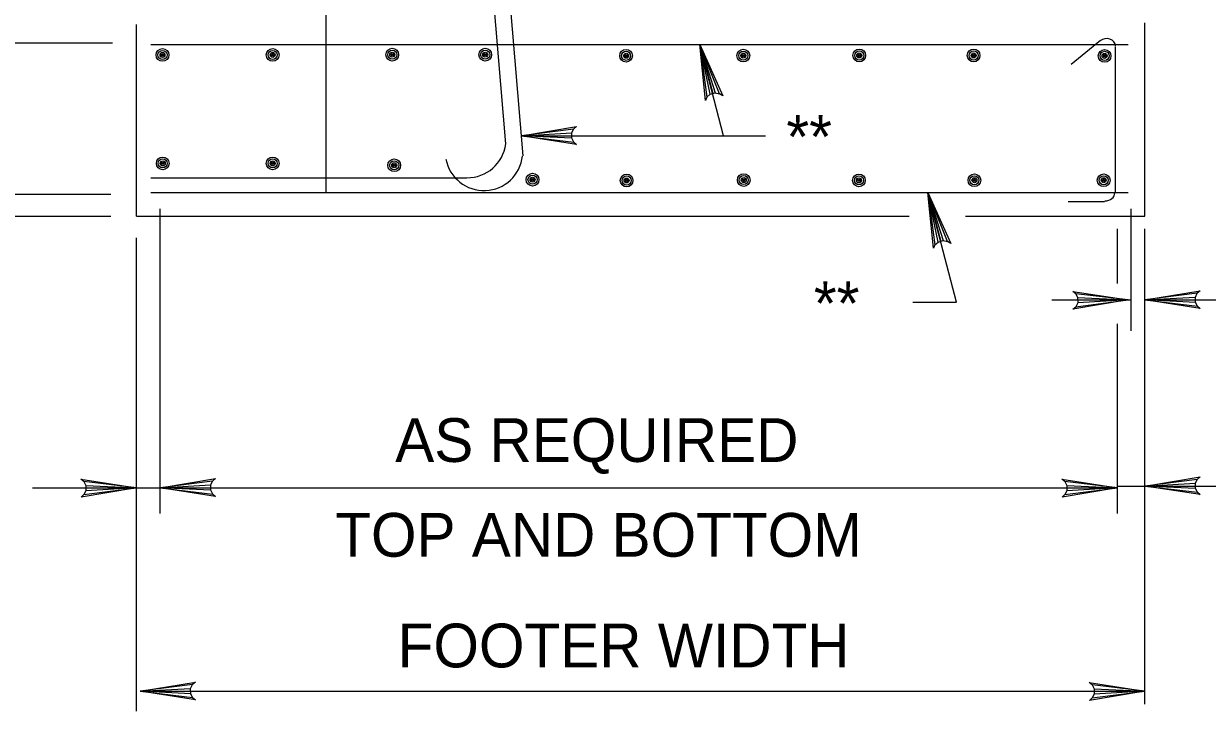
# Model space of a CAD drawing. Extents: x 639011 to 639866, y 298840 to 300028.
# Drawn here: x 639301.8 to 639383, y 299490 to 299537.2 of the extents above; entities that cross this region are included whole.
import ezdxf

# ---------------------------------------------------------------- set-up
doc = ezdxf.new("R2010")
doc.units = 0
doc.layers.add('2', color=7, linetype='Continuous')

msp = doc.modelspace()

# ---------------------------------------------------------------- linework, layer by layer
at = {"layer": '2'}
for p, q in [((639331.736, 299566.393), (639334.86, 299528.911)), ((639334.303, 299548.842), (639336.053, 299528.092)), ((639322.553, 299525.592), (639322.553, 299543.967)), ((639309.553, 299523.967), (639309.553, 299537.092)), ((639378.678, 299523.967), (639378.678, 299537.217)), ((639293.678, 299535.842), (639307.928, 299535.842)), ((639310.553, 299535.717), (639377.553, 299535.717)), ((639349.803, 299529.467), (639348.178, 299535.717)), ((639348.892, 299532.313), (639348.178, 299535.717)), ((639348.178, 299535.717), (639348.669, 299532.115)), ((639348.563, 299531.889), (639348.178, 299535.717)), ((639348.178, 299535.717), (639349.241, 299532.407)), ((639349.527, 299532.349), (639348.178, 299535.717)), ((639348.178, 299535.717), (639349.747, 299532.204)), ((639348.178, 299535.717), (639349.066, 299532.36)), ((639375.635, 299535.99), (639373.635, 299534.365)), ((639376.678, 299525.592), (639376.678, 299535.592)), ((639348.669, 299532.115), (639348.563, 299531.889)), ((639348.669, 299532.115), (639348.892, 299532.313)), ((639348.892, 299532.313), (639349.241, 299532.407)), ((639349.241, 299532.407), (639349.527, 299532.349)), ((639349.747, 299532.204), (639349.527, 299532.349)), ((639335.928, 299529.467), (639339.722, 299530.101)), ((639339.526, 299529.925), (639335.928, 299529.467)), ((639339.399, 299529.663), (639339.526, 299529.925)), ((639339.722, 299530.101), (639339.526, 299529.925)), ((639335.928, 299529.467), (639339.399, 299529.663)), ((639335.928, 299529.467), (639339.4, 299529.482)), ((639335.928, 299529.467), (639352.678, 299529.467)), ((639339.401, 299529.301), (639335.928, 299529.467)), ((639335.928, 299529.467), (639339.537, 299529.036)), ((639339.73, 299528.877), (639335.928, 299529.467)), ((639339.401, 299529.301), (639339.399, 299529.663)), ((639339.537, 299529.036), (639339.401, 299529.301)), ((639339.537, 299529.036), (639339.73, 299528.877)), ((639310.553, 299526.592), (639332.207, 299526.592)), ((639277.303, 299525.467), (639307.803, 299525.467)), ((639310.553, 299525.592), (639377.553, 299525.592)), ((639365.765, 299518.071), (639363.803, 299525.592)), ((639364.519, 299522.189), (639363.803, 299525.592)), ((639363.803, 299525.592), (639364.297, 299521.991)), ((639364.191, 299521.764), (639363.803, 299525.592)), ((639363.803, 299525.592), (639364.869, 299522.283)), ((639365.154, 299522.226), (639363.803, 299525.592)), ((639363.803, 299525.592), (639365.375, 299522.08)), ((639363.803, 299525.592), (639364.694, 299522.236)), ((639373.428, 299524.967), (639375.928, 299524.967)), ((639311.178, 299503.592), (639311.178, 299524.467)), ((639377.759, 299516.092), (639377.759, 299524.467)), ((639266.178, 299523.967), (639307.803, 299523.967)), ((639309.553, 299523.967), (639362.53, 299523.967)), ((639366.384, 299523.967), (639378.678, 299523.967)), ((639309.553, 299490.026), (639309.553, 299522.467)), ((639376.803, 299519.342), (639376.803, 299523.092)), ((639378.678, 299490.526), (639378.678, 299523.092)), ((639364.297, 299521.991), (639364.191, 299521.764)), ((639364.297, 299521.991), (639364.519, 299522.189)), ((639364.519, 299522.189), (639364.869, 299522.283)), ((639364.869, 299522.283), (639365.154, 299522.226)), ((639365.375, 299522.08), (639365.154, 299522.226)), ((639373.944, 299518.647), (639373.751, 299518.807)), ((639373.751, 299518.807), (639377.553, 299518.217)), ((639373.944, 299518.647), (639374.079, 299518.383)), ((639377.553, 299518.217), (639373.944, 299518.647)), ((639374.079, 299518.383), (639377.553, 299518.217)), ((639374.079, 299518.383), (639374.082, 299518.021)), ((639378.678, 299518.217), (639382.472, 299518.851)), ((639382.276, 299518.675), (639378.678, 299518.217)), ((639378.678, 299518.217), (639382.149, 299518.413)), ((639382.149, 299518.413), (639382.276, 299518.675)), ((639382.151, 299518.051), (639382.149, 299518.413)), ((639382.472, 299518.851), (639382.276, 299518.675)), ((639362.782, 299518.071), (639365.765, 299518.071)), ((639372.303, 299518.217), (639377.759, 299518.217)), ((639377.553, 299518.217), (639373.758, 299517.582)), ((639373.758, 299517.582), (639373.954, 299517.759)), ((639373.954, 299517.759), (639377.553, 299518.217)), ((639374.082, 299518.021), (639373.954, 299517.759)), ((639377.553, 299518.217), (639374.081, 299518.202)), ((639377.553, 299518.217), (639374.082, 299518.021)), ((639378.678, 299518.217), (639382.15, 299518.232)), ((639378.678, 299518.217), (639406.277, 299518.217)), ((639382.151, 299518.051), (639378.678, 299518.217)), ((639378.678, 299518.217), (639382.287, 299517.786)), ((639382.48, 299517.627), (639378.678, 299518.217)), ((639382.287, 299517.786), (639382.151, 299518.051)), ((639382.287, 299517.786), (639382.48, 299517.627)), ((639376.803, 299503.592), (639376.803, 299516.592)), ((639302.428, 299505.342), (639311.178, 299505.342)), ((639305.944, 299505.772), (639305.751, 299505.932)), ((639305.751, 299505.932), (639309.553, 299505.342)), ((639309.553, 299505.342), (639305.758, 299504.707)), ((639305.944, 299505.772), (639306.079, 299505.508)), ((639309.553, 299505.342), (639305.944, 299505.772)), ((639305.954, 299504.884), (639309.553, 299505.342)), ((639306.079, 299505.508), (639309.553, 299505.342)), ((639306.079, 299505.508), (639306.082, 299505.146)), ((639309.553, 299505.342), (639306.081, 299505.327)), ((639309.553, 299505.342), (639306.082, 299505.146)), ((639311.178, 299505.342), (639314.972, 299505.976)), ((639314.776, 299505.8), (639311.178, 299505.342)), ((639311.178, 299505.342), (639314.649, 299505.538)), ((639311.178, 299505.342), (639314.65, 299505.357)), ((639311.178, 299505.342), (639376.803, 299505.342)), ((639314.651, 299505.176), (639311.178, 299505.342)), ((639311.178, 299505.342), (639314.787, 299504.911)), ((639314.98, 299504.752), (639311.178, 299505.342)), ((639314.649, 299505.538), (639314.776, 299505.8)), ((639314.651, 299505.176), (639314.649, 299505.538)), ((639314.972, 299505.976), (639314.776, 299505.8)), ((639373.194, 299505.772), (639373.001, 299505.932)), ((639373.001, 299505.932), (639376.803, 299505.342)), ((639376.803, 299505.342), (639373.008, 299504.707)), ((639373.194, 299505.772), (639373.329, 299505.508)), ((639376.803, 299505.342), (639373.194, 299505.772)), ((639373.204, 299504.884), (639376.803, 299505.342)), ((639373.329, 299505.508), (639376.803, 299505.342)), ((639373.329, 299505.508), (639373.332, 299505.146)), ((639376.803, 299505.342), (639373.331, 299505.327)), ((639376.803, 299505.342), (639373.332, 299505.146)), ((639376.803, 299505.467), (639386.678, 299505.467)), ((639378.678, 299505.467), (639382.472, 299506.101)), ((639382.276, 299505.925), (639378.678, 299505.467)), ((639378.678, 299505.467), (639382.149, 299505.663)), ((639378.678, 299505.467), (639382.15, 299505.482)), ((639382.151, 299505.301), (639378.678, 299505.467)), ((639378.678, 299505.467), (639382.287, 299505.036)), ((639382.48, 299504.877), (639378.678, 299505.467)), ((639382.149, 299505.663), (639382.276, 299505.925)), ((639382.151, 299505.301), (639382.149, 299505.663)), ((639382.472, 299506.101), (639382.276, 299505.925)), ((639305.758, 299504.707), (639305.954, 299504.884)), ((639306.082, 299505.146), (639305.954, 299504.884)), ((639314.787, 299504.911), (639314.651, 299505.176)), ((639314.787, 299504.911), (639314.98, 299504.752)), ((639373.008, 299504.707), (639373.204, 299504.884)), ((639373.332, 299505.146), (639373.204, 299504.884)), ((639382.287, 299505.036), (639382.151, 299505.301)), ((639382.287, 299505.036), (639382.48, 299504.877)), ((639309.803, 299491.401), (639313.597, 299492.035)), ((639313.401, 299491.859), (639309.803, 299491.401)), ((639309.803, 299491.401), (639313.274, 299491.597)), ((639313.274, 299491.597), (639313.401, 299491.859)), ((639313.276, 299491.235), (639313.274, 299491.597)), ((639313.597, 299492.035), (639313.401, 299491.859)), ((639375.069, 299491.831), (639374.876, 299491.991)), ((639374.876, 299491.991), (639378.678, 299491.401)), ((639375.069, 299491.831), (639375.204, 299491.567)), ((639378.678, 299491.401), (639375.069, 299491.831)), ((639375.204, 299491.567), (639378.678, 299491.401)), ((639375.204, 299491.567), (639375.207, 299491.205)), ((639309.803, 299491.401), (639313.275, 299491.416)), ((639309.803, 299491.401), (639378.678, 299491.401)), ((639313.276, 299491.235), (639309.803, 299491.401)), ((639309.803, 299491.401), (639313.412, 299490.97)), ((639313.605, 299490.811), (639309.803, 299491.401)), ((639313.412, 299490.97), (639313.276, 299491.235)), ((639313.412, 299490.97), (639313.605, 299490.811)), ((639378.678, 299491.401), (639374.883, 299490.766)), ((639374.883, 299490.766), (639375.079, 299490.943)), ((639375.079, 299490.943), (639378.678, 299491.401)), ((639375.207, 299491.205), (639375.079, 299490.943)), ((639378.678, 299491.401), (639375.206, 299491.386)), ((639378.678, 299491.401), (639375.207, 299491.205))]:
    msp.add_line(p, q, dxfattribs=at)
for centre, radius in [((639311.345, 299535.011), 0.437), ((639311.345, 299535.011), 0.437), ((639318.897, 299535.015), 0.437), ((639318.897, 299535.015), 0.437), ((639327.096, 299535.029), 0.437), ((639327.096, 299535.029), 0.437), ((639333.467, 299535.029), 0.437), ((639333.467, 299535.029), 0.437), ((639343.126, 299534.954), 0.437), ((639343.126, 299534.954), 0.437), ((639351.16, 299534.967), 0.437), ((639351.16, 299534.967), 0.437), ((639359.108, 299534.975), 0.437), ((639359.108, 299534.975), 0.437), ((639366.948, 299534.975), 0.437), ((639366.948, 299534.975), 0.437), ((639375.926, 299534.947), 0.437), ((639375.926, 299534.947), 0.437), ((639311.345, 299535.011), 0.312), ((639311.345, 299535.011), 0.312), ((639311.345, 299535.011), 0.17), ((639311.345, 299535.011), 0.17), ((639311.345, 299535.011), 0.086), ((639311.345, 299535.011), 0.086), ((639311.345, 299535.011), 0.0368), ((639311.345, 299535.011), 0.0368), ((639318.897, 299535.015), 0.312), ((639318.897, 299535.015), 0.312), ((639318.897, 299535.015), 0.17), ((639318.897, 299535.015), 0.17), ((639318.897, 299535.015), 0.086), ((639318.897, 299535.015), 0.086), ((639318.897, 299535.015), 0.0368), ((639318.897, 299535.015), 0.0368), ((639327.096, 299535.029), 0.312), ((639327.096, 299535.029), 0.312), ((639327.096, 299535.029), 0.17), ((639327.096, 299535.029), 0.17), ((639327.096, 299535.029), 0.086), ((639327.096, 299535.029), 0.086), ((639327.096, 299535.029), 0.0368), ((639327.096, 299535.029), 0.0368), ((639333.467, 299535.029), 0.312), ((639333.467, 299535.029), 0.312), ((639333.467, 299535.029), 0.17), ((639333.467, 299535.029), 0.17), ((639333.467, 299535.029), 0.086), ((639333.467, 299535.029), 0.086), ((639333.467, 299535.029), 0.0368), ((639333.467, 299535.029), 0.0368), ((639343.126, 299534.954), 0.312), ((639343.126, 299534.954), 0.312), ((639343.126, 299534.954), 0.17), ((639343.126, 299534.954), 0.17), ((639343.126, 299534.954), 0.086), ((639343.126, 299534.954), 0.086), ((639343.126, 299534.954), 0.0368), ((639343.126, 299534.954), 0.0368), ((639351.16, 299534.967), 0.312), ((639351.16, 299534.967), 0.312), ((639351.16, 299534.967), 0.17), ((639351.16, 299534.967), 0.17), ((639351.16, 299534.967), 0.086), ((639351.16, 299534.967), 0.086), ((639351.16, 299534.967), 0.0368), ((639351.16, 299534.967), 0.0368), ((639359.108, 299534.975), 0.312), ((639359.108, 299534.975), 0.312), ((639359.108, 299534.975), 0.17), ((639359.108, 299534.975), 0.17), ((639359.108, 299534.975), 0.086), ((639359.108, 299534.975), 0.086), ((639359.108, 299534.975), 0.0368), ((639359.108, 299534.975), 0.0368), ((639366.948, 299534.975), 0.312), ((639366.948, 299534.975), 0.312), ((639366.948, 299534.975), 0.17), ((639366.948, 299534.975), 0.17), ((639366.948, 299534.975), 0.086), ((639366.948, 299534.975), 0.086), ((639366.948, 299534.975), 0.0368), ((639366.948, 299534.975), 0.0368), ((639375.926, 299534.947), 0.312), ((639375.926, 299534.947), 0.312), ((639375.926, 299534.947), 0.17), ((639375.926, 299534.947), 0.17), ((639375.926, 299534.947), 0.086), ((639375.926, 299534.947), 0.086), ((639375.926, 299534.947), 0.0368), ((639375.926, 299534.947), 0.0368), ((639311.362, 299527.579), 0.437), ((639311.362, 299527.579), 0.437), ((639311.362, 299527.579), 0.312), ((639311.362, 299527.579), 0.312), ((639311.362, 299527.579), 0.17), ((639311.362, 299527.579), 0.17), ((639311.362, 299527.579), 0.086), ((639311.362, 299527.579), 0.086), ((639311.362, 299527.579), 0.0368), ((639311.362, 299527.579), 0.0368), ((639318.895, 299527.579), 0.437), ((639318.895, 299527.579), 0.437), ((639318.895, 299527.579), 0.312), ((639318.895, 299527.579), 0.312), ((639318.895, 299527.579), 0.17), ((639318.895, 299527.579), 0.17), ((639318.895, 299527.579), 0.086), ((639318.895, 299527.579), 0.086), ((639318.895, 299527.579), 0.0368), ((639318.895, 299527.579), 0.0368), ((639327.228, 299527.451), 0.437), ((639327.228, 299527.451), 0.437), ((639327.228, 299527.451), 0.312), ((639327.228, 299527.451), 0.312), ((639327.228, 299527.451), 0.17), ((639327.228, 299527.451), 0.17), ((639327.228, 299527.451), 0.086), ((639327.228, 299527.451), 0.086), ((639327.228, 299527.451), 0.0368), ((639327.228, 299527.451), 0.0368), ((639336.711, 299526.464), 0.437), ((639336.711, 299526.464), 0.437), ((639336.711, 299526.464), 0.312), ((639336.711, 299526.464), 0.312), ((639336.711, 299526.464), 0.17), ((639336.711, 299526.464), 0.17), ((639336.711, 299526.464), 0.086), ((639336.711, 299526.464), 0.086), ((639336.711, 299526.464), 0.0368), ((639336.711, 299526.464), 0.0368), ((639343.157, 299526.407), 0.437), ((639343.157, 299526.407), 0.437), ((639343.157, 299526.407), 0.312), ((639343.157, 299526.407), 0.312), ((639343.157, 299526.407), 0.17), ((639343.157, 299526.407), 0.17), ((639343.157, 299526.407), 0.086), ((639343.157, 299526.407), 0.086), ((639343.157, 299526.407), 0.0368), ((639343.157, 299526.407), 0.0368), ((639351.191, 299526.435), 0.437), ((639351.191, 299526.435), 0.437), ((639351.191, 299526.435), 0.312), ((639351.191, 299526.435), 0.312), ((639351.191, 299526.435), 0.17), ((639351.191, 299526.435), 0.17), ((639351.191, 299526.435), 0.086), ((639351.191, 299526.435), 0.086), ((639351.191, 299526.435), 0.0368), ((639351.191, 299526.435), 0.0368), ((639359.085, 299526.414), 0.437), ((639359.085, 299526.414), 0.437), ((639359.085, 299526.414), 0.312), ((639359.085, 299526.414), 0.312), ((639359.085, 299526.414), 0.17), ((639359.085, 299526.414), 0.17), ((639359.085, 299526.414), 0.086), ((639359.085, 299526.414), 0.086), ((639359.085, 299526.414), 0.0368), ((639359.085, 299526.414), 0.0368), ((639367.003, 299526.425), 0.437), ((639367.003, 299526.425), 0.437), ((639367.003, 299526.425), 0.312), ((639367.003, 299526.425), 0.312), ((639367.003, 299526.425), 0.17), ((639367.003, 299526.425), 0.17), ((639367.003, 299526.425), 0.086), ((639367.003, 299526.425), 0.086), ((639367.003, 299526.425), 0.0368), ((639367.003, 299526.425), 0.0368), ((639375.864, 299526.425), 0.437), ((639375.864, 299526.425), 0.437), ((639375.864, 299526.425), 0.312), ((639375.864, 299526.425), 0.312), ((639375.864, 299526.425), 0.17), ((639375.864, 299526.425), 0.17), ((639375.864, 299526.425), 0.086), ((639375.864, 299526.425), 0.086), ((639375.864, 299526.425), 0.0368), ((639375.864, 299526.425), 0.0368)]:
    msp.add_circle(centre, radius, dxfattribs=at)
for centre, start, end in [((639332.239, 299529.249), 269.31781, 352.70968), ((639333.384, 299528.37), 190.72012, 353.83139)]:
    msp.add_arc(centre, 2.655, start, end, dxfattribs=at)
for centre, major_axis, start_param, end_param in [((639376.064, 299535.638), (0.608, 0), 0, 2.356194), ((639375.951, 299525.558), (-0.675, 0), 1.570796, 3.141593)]:
    msp.add_ellipse(centre, major_axis=major_axis, ratio=0.818182, start_param=start_param, end_param=end_param, dxfattribs=at)

# ---------------------------------------------------------------- texts
for s, p in [('**', (639354.113, 299527.902)), ('**', (639355.998, 299516.485)), ('AS REQUIRED ', (639327.299, 299507.117)), ('TOP AND BOTTOM', (639323.186, 299500.622)), ('FOOTER WIDTH', (639327.467, 299493.037))]:
    msp.add_text(s, height=3, dxfattribs=at).set_placement(p)

doc.saveas('drawing.dxf')
